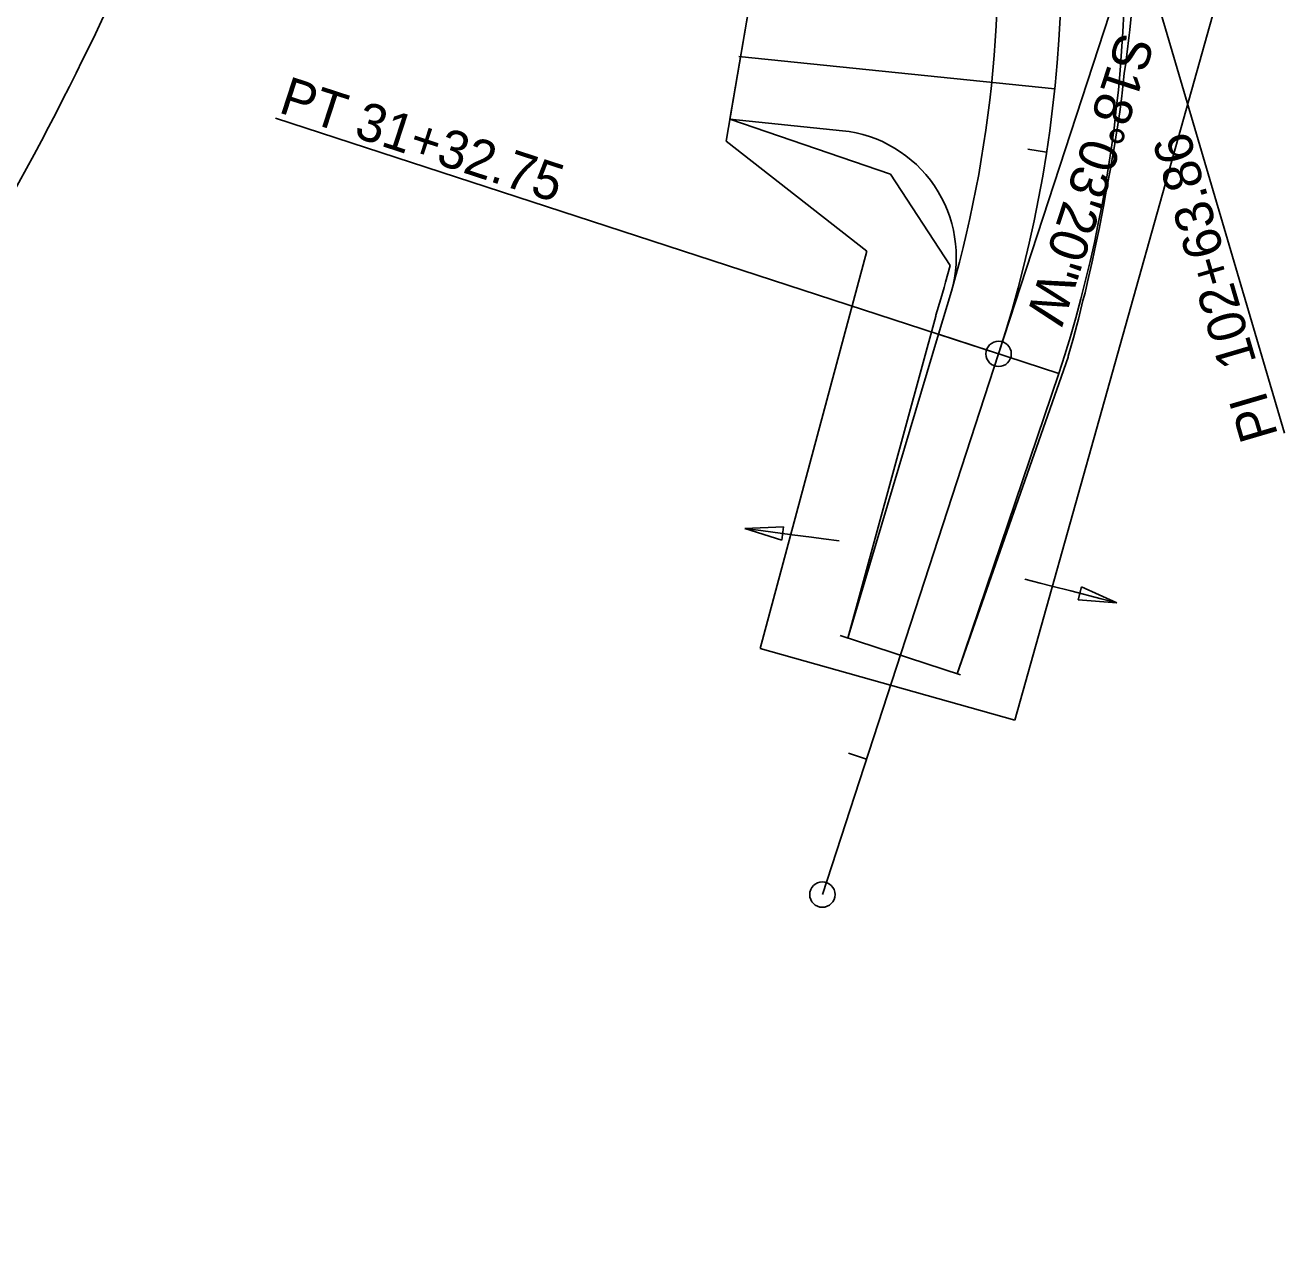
# Model space of a CAD drawing. Extents: x 1 to 1477871, y 1 to 1872901.
# Drawn here: x 1443824.9 to 1444023.8, y 1854698.4 to 1854893.5 of the extents above; entities that cross this region are included whole.
import ezdxf

# ---------------------------------------------------------------- set-up
doc = ezdxf.new("R2010")
doc.units = 0
for name, color, linetype in [('R_Drive', 7, 'Continuous'), ('R_Floodplain', 7, 'Continuous'), ('R_Horz Alg', 7, 'Continuous'), ('R_Horz Alg Annot', 7, 'Continuous'), ('R_No Plot', 7, 'Continuous'), ('R_Proposed Const Limits_Fill', 7, 'Continuous'), ('R_Proposed Road_Lane', 7, 'Continuous'), ('R_Temp Easement', 7, 'Continuous'), ('R_Water', 7, 'Continuous')]:
    doc.layers.add(name, color=color, linetype=linetype)

msp = doc.modelspace()

# ---------------------------------------------------------------- linework, layer by layer
at = {"layer": 'R_Drive'}
for p, q in [((1443936.07, 1854878.66), (1443939.47, 1854898.41)), ((1443953.83, 1854876.84), (1443936.06, 1854878.66))]:
    msp.add_line(p, q, dxfattribs=at)
msp.add_arc((1443951.79, 1854856.94), 20, 344.0479, 84.1498, dxfattribs=at)
at = {"layer": 'R_Floodplain'}
msp.add_open_spline([(1444534.23, 1857777.84), (1444398.78, 1857609.12), (1444367.89, 1857131.47), (1444306.1, 1856808.28), (1444134.95, 1856378.26), (1444024.62, 1856227.92), (1443837.91, 1855964.82), (1443664.53, 1855852.06), (1443479.03, 1855867.82), (1443335.96, 1855886.01), (1443298.37, 1855854.49), (1443356.57, 1855756.28), (1443606.51, 1855482.27), (1443757.19, 1855307.33), (1443863.11, 1855113.58), (1443878.59, 1855007.91), (1443849.87, 1854910.07), (1443760.66, 1854753.08), (1443429.28, 1854512.04), (1443240.87, 1854371.16), (1443115.26, 1854254.04), (1443060.94, 1853889.1), (1443099.99, 1853680.31), (1443032.09, 1853386.66), (1443001.54, 1853198.25), (1444534.23, 1857777.84), (1443001.54, 1853198.25)], degree=3, dxfattribs=at)
at = {"layer": 'R_Horz Alg'}
msp.add_line((1443978.48, 1854841.64), (1443950.67, 1854756.34), dxfattribs=at)
msp.add_line((1443978.48, 1854841.64), (1443950.67, 1854756.34), dxfattribs=at)
msp.add_arc((1443787.34, 1854903.95), 201.04, 341.9445, 14.8311, dxfattribs=at)
msp.add_arc((1443787.34, 1854903.95), 201.04, 341.9445, 14.8311, dxfattribs=at)
at = {"layer": 'R_Horz Alg Annot'}
msp.add_line((1443996.87, 1854898.05), (1443978.48, 1854841.64), dxfattribs=at)
for points in [[(1443989.71, 1854944.24), (1444023.56, 1854829.11)], [(1443978.48, 1854841.64), (1443864.39, 1854878.83)], [(1443983.09, 1854873.92), (1443986.05, 1854873.46)], [(1443954.78, 1854778.63), (1443957.63, 1854777.7)]]:
    msp.add_lwpolyline(points, dxfattribs=at)
for centre in [(1443978.48, 1854841.64), (1443950.67, 1854756.34)]:
    msp.add_circle(centre, 2, dxfattribs=at)
at = {"layer": 'R_No Plot'}
for p, q in [((1443987.33, 1854883.46), (1443937.51, 1854888.56)), ((1443987.99, 1854838.54), (1443968.97, 1854844.74)), ((1443972.49, 1854791), (1443953.47, 1854797.2))]:
    msp.add_line(p, q, dxfattribs=at)
at = {"layer": 'R_Proposed Const Limits_Fill'}
for points in [[(1443999.41, 1854894.93), (1443999.18, 1854892.77), (1443999.08, 1854891.9), (1443998.71, 1854888.88), (1443998.53, 1854887.52), (1443998.31, 1854885.86), (1443997.99, 1854882.84), (1443997.92, 1854882.29), (1443997.58, 1854879.83), (1443997.16, 1854877.08), (1443997.12, 1854876.83), (1443996.64, 1854873.83), (1443996.31, 1854871.89), (1443996.12, 1854870.84), (1443995.57, 1854867.86), (1443995.35, 1854866.72), (1443995.03, 1854864.87), (1443994.45, 1854861.89), (1443994.38, 1854861.55), (1443993.84, 1854858.92), (1443993.3, 1854856.41), (1443993.2, 1854855.96), (1443992.52, 1854853), (1443992.12, 1854851.29), (1443991.79, 1854850.06), (1443991.06, 1854847.11), (1443990.83, 1854846.19), (1443990.29, 1854844.17), (1443989.47, 1854841.25), (1443989.43, 1854841.11), (1443971.95, 1854791.18), (1443971.95, 1854791.18)], [(1443936.07, 1854878.66), (1443961.41, 1854869.96), (1443970.81, 1854855.59), (1443970.12, 1854852.96), (1443969.89, 1854852.13), (1443969.38, 1854850.33), (1443968.6, 1854847.72), (1443968.57, 1854847.6), (1443954.7, 1854796.8), (1443954.7, 1854796.8)]]:
    msp.add_lwpolyline(points, dxfattribs=at)
at = {"layer": 'R_Proposed Road_Lane'}
for p, q in [((1443968.97, 1854844.74), (1443954.7, 1854796.8)), ((1443987.99, 1854838.54), (1443971.95, 1854791.18))]:
    msp.add_line(p, q, dxfattribs=at)
for radius, end in [(211.04, 8.4876), (191.04, 4.6393)]:
    msp.add_arc((1443787.34, 1854903.95), radius, 341.9445, end, dxfattribs=at)
at = {"layer": 'R_Temp Easement'}
for p, q in [((1443981.03, 1854783.84), (1444023.78, 1854936.11)), ((1443935.47, 1854875.19), (1443940.12, 1854902.17)), ((1443935.47, 1854875.19), (1443957.7, 1854857.86)), ((1443957.7, 1854857.86), (1443940.85, 1854795.17)), ((1443940.85, 1854795.17), (1443981.03, 1854783.84))]:
    msp.add_line(p, q, dxfattribs=at)
at = {"layer": 'R_Water'}
for p, q in [((1443944.55, 1854814.35), (1443938.46, 1854814.08)), ((1443938.46, 1854814.08), (1443944.27, 1854812.25)), ((1443944.27, 1854812.25), (1443944.55, 1854814.35)), ((1443991.57, 1854804.89), (1443991.04, 1854802.84)), ((1443997.12, 1854802.38), (1443991.57, 1854804.89)), ((1443991.04, 1854802.84), (1443997.12, 1854802.38))]:
    msp.add_line(p, q, dxfattribs=at)
for points in [[(1443953.34, 1854812.13), (1443950.84, 1854812.45), (1443948.97, 1854812.7), (1443945.9, 1854813.1), (1443940.96, 1854813.75), (1443938.46, 1854814.08)], [(1443982.59, 1854806.1), (1443985.03, 1854805.48), (1443986.85, 1854805.01), (1443989.85, 1854804.24), (1443994.68, 1854803), (1443997.12, 1854802.37)]]:
    msp.add_lwpolyline(points, dxfattribs=at)

# ---------------------------------------------------------------- texts
at = {"layer": 'R_Horz Alg Annot'}
for s, rotation, p in [('S18%%d03\'20"W', 251.9445, (1443997.45, 1854892.61)), ('PT 31+32.75', 341.9445, (1443864.7, 1854879.78)), ('PI  102+63.86', 106.3833, (1444022.6, 1854828.83))]:
    msp.add_text(s, height=6, rotation=rotation, dxfattribs=at).set_placement(p)

doc.saveas('drawing.dxf')
